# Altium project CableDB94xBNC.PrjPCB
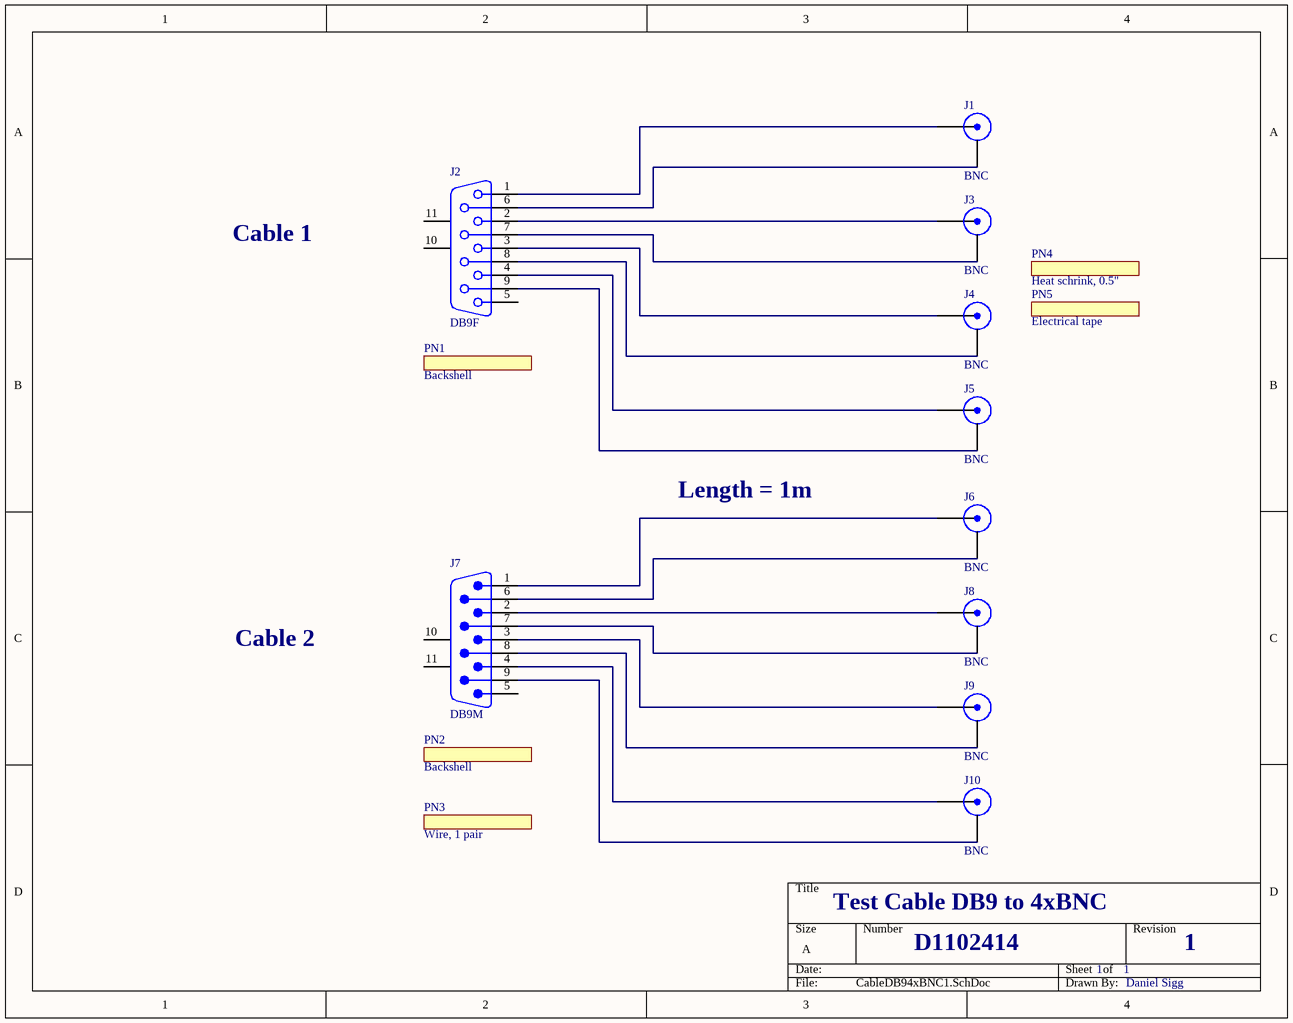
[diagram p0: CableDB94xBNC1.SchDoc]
Title: D1102414
1 sheet, 15 parts. Net scope: global (net labels, ports and power ports of the same name join across sheets).

## Sheet CableDB94xBNC1.SchDoc: D1102414
size A; Engineer: Daniel Sigg; Revision: 1; PageSetup: Record=PageOptions|CenterHorizontal=True|CenterVertical=True|PrintScale=1.12|XCorrection=1.00|YCorrection=1.00|PrintKind=0|BorderSize=5000000|LeftOffset=0|BottomOffset=0|Orientation=2|PaperLength=1000|PaperWidth=1000|Scale=100|PaperSource=7|PrintQuality=-4|MediaType=1|DitherType=10|PaperKind=Letter|PrintScaleMode=1

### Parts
J1  BNC  [BNC2]
J2  DB9F  [DB9F-RA]
J3  BNC  [BNC2]
J4  BNC  [BNC2]
J5  BNC  [BNC2]
J6  BNC  [BNC2]
J7  DB9M  [DB9M-RA]
J8  BNC  [BNC2]
J9  BNC  [BNC2]
J10  BNC  [BNC2]
PN1  Backshell  (mechanical)
PN2  Backshell  (mechanical)
PN3  Wire, 1 pair  (mechanical)
PN4  Heat schrink, 0.5"  (mechanical)
PN5  Electrical tape  (mechanical)

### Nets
NetJ1_1: J1.1(X) J2.1
NetJ1_2: J1.2(Y) J2.6
NetJ2_2: J2.2 J3.1(X)
NetJ2_3: J2.3 J4.1(X)
NetJ2_4: J2.4 J5.1(X)
NetJ2_7: J2.7 J3.2(Y)
NetJ2_8: J2.8 J4.2(Y)
NetJ2_9: J2.9 J5.2(Y)
NetJ6_1: J6.1(X) J7.1
NetJ6_2: J6.2(Y) J7.6
NetJ7_2: J7.2 J8.1(X)
NetJ7_3: J7.3 J9.1(X)
NetJ7_4: J7.4 J10.1(X)
NetJ7_7: J7.7 J8.2(Y)
NetJ7_8: J7.8 J9.2(Y)
NetJ7_9: J7.9 J10.2(Y)

Not connected (* = marked no-connect by the designer): J2 5 10(MH1) 11(MH2); J7 5 10(MH1) 11(MH2)

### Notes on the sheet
- Cable 1
- Length = 1m
- Cable 2
- Test Cable DB9 to 4xBNC
- D1102414
- 1
- Daniel Sigg

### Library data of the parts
J1 J3-J6 J8-J10 = BNC: BNC, PCB Mount, Right Angle; Part Number: A32340-ND
J2 = DB9F: Receptacle Assembly, 9 Position, Right Angle, .318 Series; Part Number: A32510-ND
J7 = DB9M: Plug Assembly, 9 Position, Right Angle, .318 Series; Part Number: A32507-ND
PN1 PN2 = Partlist: Additional part number; Part Number: MDBS09-ND
PN3 = Partlist: Additional part number; Part Number: A120-100-ND
PN4 = Partlist: Additional part number; Part Number: RNF012K-ND
PN5 = Partlist: Additional part number; Part Number: 3M1700-ND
